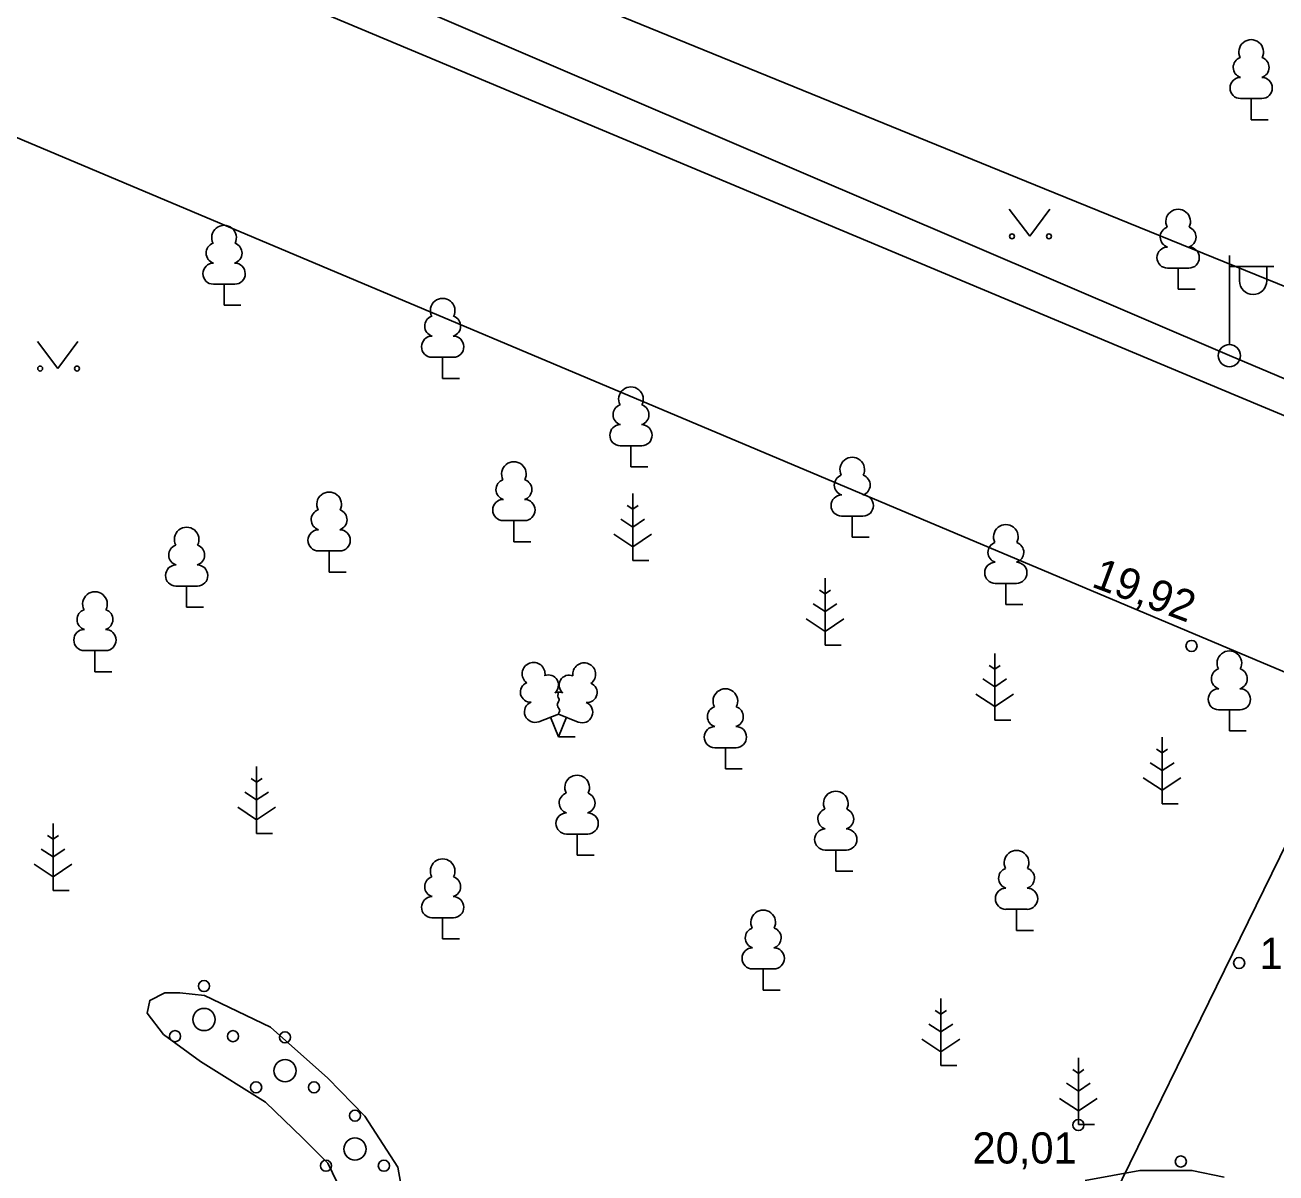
# Model space of a CAD drawing. Extents: x 713497 to 713863, y 6590062 to 6590327.
# Drawn here: x 713775.3 to 713803.4, y 6590210.37 to 6590236.16 of the extents above; entities that cross this region are included whole.
import ezdxf

# ---------------------------------------------------------------- set-up
doc = ezdxf.new("R2010")
doc.units = 0
for name, color, linetype in [('HALJASTUS', 7, 'Continuous'), ('KORGUS', 7, 'Continuous'), ('KPKAABEL', 7, 'Continuous'), ('MPKAABEL', 7, 'Continuous'), ('POST', 7, 'Continuous'), ('PUU', 7, 'Continuous'), ('SITRASS', 7, 'Continuous'), ('TEE', 7, 'Continuous')]:
    doc.layers.add(name, color=color, linetype=linetype)

msp = doc.modelspace()

# ---------------------------------------------------------------- linework, layer by layer
at = {"layer": 'HALJASTUS'}
for p, q in [((713797.407, 6590232.017), (713797.87, 6590231.41)), ((713797.87, 6590231.41), (713798.316, 6590232.017)), ((713775.577, 6590229.047), (713776.04, 6590228.44)), ((713776.04, 6590228.44), (713776.486, 6590229.047))]:
    msp.add_line(p, q, dxfattribs=at)
for points in [[(713783.87, 6590209.41), (713783.67, 6590210.5), (713782.93, 6590211.65), (713782.1, 6590212.5), (713780.81, 6590213.65), (713779.33, 6590214.36), (713778.78, 6590214.42), (713778.44, 6590214.42), (713778.1, 6590214.25), (713778.04, 6590213.96), (713778.41, 6590213.48), (713779.24, 6590212.88), (713780.7, 6590211.96), (713781.53, 6590211.16), (713782.1, 6590210.59), (713782.42, 6590209.93)], [(713802.23, 6590210.28), (713801.51, 6590210.43), (713800.34, 6590210.43), (713799.11, 6590210.2)]]:
    msp.add_lwpolyline(points, dxfattribs=at)
for centre, radius in [((713797.469, 6590231.41), 0.055), ((713798.298, 6590231.41), 0.055), ((713775.639, 6590228.44), 0.055), ((713776.468, 6590228.44), 0.055), ((713779.32, 6590214.57), 0.125), ((713779.32, 6590213.82), 0.25), ((713778.67, 6590213.445), 0.125), ((713779.97, 6590213.445), 0.125), ((713781.14, 6590213.42), 0.125), ((713781.14, 6590212.67), 0.25), ((713780.49, 6590212.295), 0.125), ((713781.79, 6590212.295), 0.125), ((713782.71, 6590211.66), 0.125), ((713782.71, 6590210.91), 0.25), ((713801.26, 6590210.63), 0.125), ((713782.06, 6590210.535), 0.125), ((713783.36, 6590210.535), 0.125)]:
    msp.add_circle(centre, radius, dxfattribs=at)
at = {"layer": 'KORGUS'}
for centre in [(713801.5, 6590222.21), (713802.57, 6590215.09), (713798.96, 6590211.45)]:
    msp.add_circle(centre, 0.125, dxfattribs=at)
at = {"layer": 'KPKAABEL'}
msp.add_lwpolyline([(713794.45, 6590198.59), (713796.04, 6590202.27), (713815.88, 6590242.79)], dxfattribs=at)
at = {"layer": 'MPKAABEL'}
for points in [[(713802.35, 6590228.73), (713777.08, 6590239.56), (713776.78, 6590239.5)], [(713830.25, 6590216.56), (713828.46, 6590217.3), (713809.94, 6590225.53), (713802.35, 6590228.73)]]:
    msp.add_lwpolyline(points, dxfattribs=at)
at = {"layer": 'POST'}
for p, q in [((713802.35, 6590228.98), (713802.35, 6590230.98)), ((713802.35, 6590230.73), (713803.35, 6590230.73)), ((713802.577, 6590230.409), (713802.577, 6590230.73)), ((713803.189, 6590230.409), (713803.189, 6590230.73))]:
    msp.add_line(p, q, dxfattribs=at)
msp.add_circle((713802.35, 6590228.73), 0.25, dxfattribs=at)
msp.add_arc((713802.883, 6590230.409), 0.306, 180, 0, dxfattribs=at)
at = {"layer": 'PUU'}
for p, q in [((713803.08, 6590234.505), (713802.6, 6590234.505)), ((713802.84, 6590234.03), (713802.84, 6590234.505)), ((713803.22, 6590234.03), (713802.84, 6590234.03)), ((713801.44, 6590230.695), (713800.96, 6590230.695)), ((713801.2, 6590230.22), (713801.2, 6590230.695)), ((713780.01, 6590230.335), (713779.53, 6590230.335)), ((713779.77, 6590229.86), (713779.77, 6590230.335)), ((713801.58, 6590230.22), (713801.2, 6590230.22)), ((713780.15, 6590229.86), (713779.77, 6590229.86)), ((713784.92, 6590228.695), (713784.44, 6590228.695)), ((713784.68, 6590228.22), (713784.68, 6590228.695)), ((713785.06, 6590228.22), (713784.68, 6590228.22)), ((713789.15, 6590226.705), (713788.67, 6590226.705)), ((713788.91, 6590226.23), (713788.91, 6590226.705)), ((713789.29, 6590226.23), (713788.91, 6590226.23)), ((713788.95, 6590225.28), (713788.826, 6590225.363)), ((713788.95, 6590225.63), (713788.95, 6590224.13)), ((713789.074, 6590225.363), (713788.95, 6590225.28)), ((713794.12, 6590225.125), (713793.64, 6590225.125)), ((713793.88, 6590224.65), (713793.88, 6590225.125)), ((713786.52, 6590225.025), (713786.04, 6590225.025)), ((713786.28, 6590224.55), (713786.28, 6590225.025)), ((713788.95, 6590224.88), (713788.683, 6590225.058)), ((713789.217, 6590225.058), (713788.95, 6590224.88)), ((713786.66, 6590224.55), (713786.28, 6590224.55)), ((713788.526, 6590224.719), (713788.95, 6590224.437)), ((713788.95, 6590224.437), (713789.374, 6590224.719)), ((713794.26, 6590224.65), (713793.88, 6590224.65)), ((713782.37, 6590224.345), (713781.89, 6590224.345)), ((713782.13, 6590223.87), (713782.13, 6590224.345)), ((713789.31, 6590224.13), (713788.95, 6590224.13)), ((713782.51, 6590223.87), (713782.13, 6590223.87)), ((713793.27, 6590223.73), (713793.27, 6590222.23)), ((713779.17, 6590223.555), (713778.69, 6590223.555)), ((713778.93, 6590223.08), (713778.93, 6590223.555)), ((713793.27, 6590223.38), (713793.146, 6590223.463)), ((713793.394, 6590223.463), (713793.27, 6590223.38)), ((713797.57, 6590223.615), (713797.09, 6590223.615)), ((713797.33, 6590223.14), (713797.33, 6590223.615)), ((713793.27, 6590222.98), (713793.003, 6590223.158)), ((713793.537, 6590223.158), (713793.27, 6590222.98)), ((713797.71, 6590223.14), (713797.33, 6590223.14)), ((713779.31, 6590223.08), (713778.93, 6590223.08)), ((713792.846, 6590222.819), (713793.27, 6590222.537)), ((713793.27, 6590222.537), (713793.694, 6590222.819)), ((713777.11, 6590222.105), (713776.63, 6590222.105)), ((713776.87, 6590221.63), (713776.87, 6590222.105)), ((713793.63, 6590222.23), (713793.27, 6590222.23)), ((713797.08, 6590222.04), (713797.08, 6590220.54)), ((713797.08, 6590221.69), (713796.956, 6590221.773)), ((713797.204, 6590221.773), (713797.08, 6590221.69)), ((713777.25, 6590221.63), (713776.87, 6590221.63)), ((713797.08, 6590221.29), (713796.813, 6590221.468)), ((713797.347, 6590221.468), (713797.08, 6590221.29)), ((713796.656, 6590221.129), (713797.08, 6590220.847)), ((713797.08, 6590220.847), (713797.504, 6590221.129)), ((713786.84, 6590220.505), (713787.285, 6590220.68)), ((713787.28, 6590220.17), (713787.105, 6590220.61)), ((713787.28, 6590220.17), (713787.46, 6590220.61)), ((713787.285, 6590220.68), (713787.725, 6590220.5)), ((713802.59, 6590220.775), (713802.11, 6590220.775)), ((713802.35, 6590220.3), (713802.35, 6590220.775)), ((713797.44, 6590220.54), (713797.08, 6590220.54)), ((713787.66, 6590220.17), (713787.28, 6590220.17)), ((713800.84, 6590220.16), (713800.84, 6590218.66)), ((713802.73, 6590220.3), (713802.35, 6590220.3)), ((713791.27, 6590219.925), (713790.79, 6590219.925)), ((713791.03, 6590219.45), (713791.03, 6590219.925)), ((713800.84, 6590219.81), (713800.716, 6590219.893)), ((713800.964, 6590219.893), (713800.84, 6590219.81)), ((713780.5, 6590219.5), (713780.5, 6590218)), ((713800.84, 6590219.41), (713800.573, 6590219.588)), ((713801.107, 6590219.588), (713800.84, 6590219.41)), ((713780.5, 6590219.15), (713780.376, 6590219.233)), ((713780.624, 6590219.233), (713780.5, 6590219.15)), ((713791.41, 6590219.45), (713791.03, 6590219.45)), ((713800.416, 6590219.249), (713800.84, 6590218.967)), ((713800.84, 6590218.967), (713801.264, 6590219.249)), ((713780.5, 6590218.75), (713780.233, 6590218.928)), ((713780.767, 6590218.928), (713780.5, 6590218.75)), ((713801.2, 6590218.66), (713800.84, 6590218.66)), ((713780.076, 6590218.589), (713780.5, 6590218.307)), ((713780.5, 6590218.307), (713780.924, 6590218.589)), ((713775.93, 6590218.22), (713775.93, 6590216.72)), ((713775.93, 6590217.87), (713775.806, 6590217.953)), ((713776.054, 6590217.953), (713775.93, 6590217.87)), ((713780.86, 6590218), (713780.5, 6590218)), ((713787.94, 6590217.985), (713787.46, 6590217.985)), ((713787.7, 6590217.51), (713787.7, 6590217.985)), ((713775.93, 6590217.47), (713775.663, 6590217.648)), ((713776.197, 6590217.648), (713775.93, 6590217.47)), ((713788.08, 6590217.51), (713787.7, 6590217.51)), ((713793.75, 6590217.625), (713793.27, 6590217.625)), ((713793.51, 6590217.15), (713793.51, 6590217.625)), ((713775.506, 6590217.309), (713775.93, 6590217.027)), ((713775.93, 6590217.027), (713776.354, 6590217.309)), ((713793.89, 6590217.15), (713793.51, 6590217.15)), ((713776.29, 6590216.72), (713775.93, 6590216.72)), ((713784.92, 6590216.105), (713784.44, 6590216.105)), ((713784.68, 6590215.63), (713784.68, 6590216.105)), ((713797.81, 6590216.295), (713797.33, 6590216.295)), ((713797.57, 6590215.82), (713797.57, 6590216.295)), ((713797.95, 6590215.82), (713797.57, 6590215.82)), ((713785.06, 6590215.63), (713784.68, 6590215.63)), ((713792.12, 6590214.955), (713791.64, 6590214.955)), ((713791.88, 6590214.48), (713791.88, 6590214.955)), ((713792.26, 6590214.48), (713791.88, 6590214.48)), ((713795.87, 6590214.29), (713795.87, 6590212.79)), ((713795.87, 6590213.94), (713795.746, 6590214.023)), ((713795.994, 6590214.023), (713795.87, 6590213.94)), ((713795.87, 6590213.54), (713795.603, 6590213.718)), ((713796.137, 6590213.718), (713795.87, 6590213.54)), ((713795.446, 6590213.379), (713795.87, 6590213.097)), ((713795.87, 6590213.097), (713796.294, 6590213.379)), ((713796.23, 6590212.79), (713795.87, 6590212.79)), ((713798.96, 6590212.96), (713798.96, 6590211.46)), ((713798.96, 6590212.61), (713798.836, 6590212.693)), ((713799.084, 6590212.693), (713798.96, 6590212.61)), ((713798.96, 6590212.21), (713798.693, 6590212.388)), ((713799.227, 6590212.388), (713798.96, 6590212.21)), ((713798.536, 6590212.049), (713798.96, 6590211.767)), ((713798.96, 6590211.767), (713799.384, 6590212.049)), ((713799.32, 6590211.46), (713798.96, 6590211.46))]:
    msp.add_line(p, q, dxfattribs=at)
msp.add_lwpolyline([(713787.285, 6590221.175), (713787.265, 6590221.1), (713787.265, 6590221.08), (713787.275, 6590221.05), (713787.295, 6590221.015), (713787.3, 6590220.995), (713787.285, 6590220.96), (713787.26, 6590220.91), (713787.255, 6590220.885), (713787.26, 6590220.87), (713787.27, 6590220.84), (713787.305, 6590220.78), (713787.31, 6590220.76), (713787.305, 6590220.74), (713787.29, 6590220.705), (713787.285, 6590220.68)], dxfattribs=at)
for centre, radius, start, end in [((713802.84, 6590235.55), 0.277, 332.5799, 207.4201), ((713802.67, 6590235.203), 0.233, 109.0217, 253.1415), ((713803.01, 6590235.203), 0.233, 286.8508, 70.9859), ((713802.603, 6590234.742), 0.238, 90.0016, 269.3953), ((713803.077, 6590234.742), 0.238, 270.6047, 89.9984), ((713801.2, 6590231.74), 0.277, 332.5799, 207.4201), ((713779.77, 6590231.38), 0.277, 332.5799, 207.4201), ((713801.03, 6590231.393), 0.233, 109.0217, 253.1415), ((713801.37, 6590231.393), 0.233, 286.8508, 70.9859), ((713779.6, 6590231.033), 0.233, 109.0217, 253.1415), ((713779.94, 6590231.033), 0.233, 286.8508, 70.9859), ((713800.963, 6590230.932), 0.238, 90.0016, 269.3953), ((713801.437, 6590230.932), 0.238, 270.6047, 89.9984), ((713779.533, 6590230.572), 0.238, 90.0016, 269.3953), ((713780.007, 6590230.572), 0.238, 270.6047, 89.9984), ((713784.68, 6590229.74), 0.277, 332.5799, 207.4201), ((713784.51, 6590229.393), 0.233, 109.0217, 253.1415), ((713784.85, 6590229.393), 0.233, 286.8508, 70.9859), ((713784.443, 6590228.932), 0.238, 90.0016, 269.3953), ((713784.917, 6590228.932), 0.238, 270.6047, 89.9984), ((713788.91, 6590227.75), 0.277, 332.5799, 207.4201), ((713788.74, 6590227.403), 0.233, 109.0217, 253.1415), ((713789.08, 6590227.403), 0.233, 286.8508, 70.9859), ((713788.673, 6590226.942), 0.238, 90.0016, 269.3953), ((713789.147, 6590226.942), 0.238, 270.6047, 89.9984), ((713786.28, 6590226.07), 0.277, 332.5799, 207.4201), ((713793.88, 6590226.17), 0.277, 332.5799, 207.4201), ((713786.11, 6590225.723), 0.233, 109.0217, 253.1415), ((713786.45, 6590225.723), 0.233, 286.8508, 70.9859), ((713793.71, 6590225.823), 0.233, 109.0217, 253.1415), ((713794.05, 6590225.823), 0.233, 286.8508, 70.9859), ((713782.13, 6590225.39), 0.277, 332.5799, 207.4201), ((713786.043, 6590225.262), 0.238, 90.0016, 269.3953), ((713786.517, 6590225.262), 0.238, 270.6047, 89.9984), ((713793.643, 6590225.362), 0.238, 90.0016, 269.3953), ((713794.117, 6590225.362), 0.238, 270.6047, 89.9984), ((713781.96, 6590225.043), 0.233, 109.0217, 253.1415), ((713782.3, 6590225.043), 0.233, 286.8508, 70.9859), ((713778.93, 6590224.6), 0.277, 332.5799, 207.4201), ((713781.893, 6590224.582), 0.238, 90.0016, 269.3953), ((713782.367, 6590224.582), 0.238, 270.6047, 89.9984), ((713797.33, 6590224.66), 0.277, 332.5799, 207.4201), ((713797.16, 6590224.313), 0.233, 109.0217, 253.1415), ((713797.5, 6590224.313), 0.233, 286.8508, 70.9859), ((713778.76, 6590224.253), 0.233, 109.0217, 253.1415), ((713779.1, 6590224.253), 0.233, 286.8508, 70.9859), ((713778.693, 6590223.792), 0.238, 90.0016, 269.3953), ((713779.167, 6590223.792), 0.238, 270.6047, 89.9984), ((713797.093, 6590223.852), 0.238, 90.0016, 269.3953), ((713797.567, 6590223.852), 0.238, 270.6047, 89.9984), ((713776.87, 6590223.15), 0.277, 332.5799, 207.4201), ((713776.7, 6590222.803), 0.233, 109.0217, 253.1415), ((713777.04, 6590222.803), 0.233, 286.8508, 70.9859), ((713776.633, 6590222.342), 0.238, 90.0016, 269.3953), ((713777.107, 6590222.342), 0.238, 270.6047, 89.9984), ((713802.35, 6590221.82), 0.277, 332.5799, 207.4201), ((713786.723, 6590221.584), 0.256, 111.5027, 232.5173), ((713786.723, 6590221.584), 0.256, 350.4856, 111.5002), ((713787.859, 6590221.575), 0.256, 67.6168, 188.6314), ((713787.859, 6590221.575), 0.256, 306.5997, 67.6143), ((713787.058, 6590221.334), 0.224, 308.5041, 111.5725), ((713787.521, 6590221.329), 0.225, 67.7016, 230.5126), ((713802.18, 6590221.473), 0.233, 109.0217, 253.1415), ((713802.52, 6590221.473), 0.233, 286.8508, 70.9859), ((713786.649, 6590221.173), 0.224, 111.4304, 274.4987), ((713787.284, 6590220.937), 0.237, 66.7655, 111.5015), ((713787.926, 6590221.163), 0.224, 264.6183, 67.6866), ((713791.03, 6590220.97), 0.277, 332.5799, 207.4201), ((713802.113, 6590221.012), 0.238, 90.0016, 269.3953), ((713802.587, 6590221.012), 0.238, 270.6047, 89.9984), ((713786.754, 6590220.728), 0.237, 111.5014, 291.5004), ((713787.815, 6590220.72), 0.237, 247.6166, 67.6155), ((713790.86, 6590220.623), 0.233, 109.0217, 253.1415), ((713791.2, 6590220.623), 0.233, 286.8508, 70.9859), ((713790.793, 6590220.162), 0.238, 90.0016, 269.3953), ((713791.267, 6590220.162), 0.238, 270.6047, 89.9984), ((713787.7, 6590219.03), 0.277, 332.5799, 207.4201), ((713787.53, 6590218.683), 0.233, 109.0217, 253.1415), ((713787.87, 6590218.683), 0.233, 286.8508, 70.9859), ((713793.51, 6590218.67), 0.277, 332.5799, 207.4201), ((713787.463, 6590218.222), 0.238, 90.0016, 269.3953), ((713787.937, 6590218.222), 0.238, 270.6047, 89.9984), ((713793.34, 6590218.323), 0.233, 109.0217, 253.1415), ((713793.68, 6590218.323), 0.233, 286.8508, 70.9859), ((713793.273, 6590217.862), 0.238, 90.0016, 269.3953), ((713793.747, 6590217.862), 0.238, 270.6047, 89.9984), ((713797.57, 6590217.34), 0.277, 332.5799, 207.4201), ((713784.68, 6590217.15), 0.277, 332.5799, 207.4201), ((713797.4, 6590216.993), 0.233, 109.0217, 253.1415), ((713797.74, 6590216.993), 0.233, 286.8508, 70.9859), ((713784.51, 6590216.803), 0.233, 109.0217, 253.1415), ((713784.85, 6590216.803), 0.233, 286.8508, 70.9859), ((713797.333, 6590216.532), 0.238, 90.0016, 269.3953), ((713797.807, 6590216.532), 0.238, 270.6047, 89.9984), ((713784.443, 6590216.342), 0.238, 90.0016, 269.3953), ((713784.917, 6590216.342), 0.238, 270.6047, 89.9984), ((713791.88, 6590216), 0.277, 332.5799, 207.4201), ((713791.71, 6590215.653), 0.233, 109.0217, 253.1415), ((713792.05, 6590215.653), 0.233, 286.8508, 70.9859), ((713791.643, 6590215.192), 0.238, 90.0016, 269.3953), ((713792.117, 6590215.192), 0.238, 270.6047, 89.9984)]:
    msp.add_arc(centre, radius, start, end, dxfattribs=at)
at = {"layer": 'SITRASS'}
msp.add_lwpolyline([(713863.358, 6590205.976), (713841.44, 6590214.83), (713823.81, 6590222.07), (713798.2, 6590232.48), (713769.43, 6590244.2), (713757.31, 6590249.39), (713740.65, 6590256.05), (713706.71, 6590269.85)], dxfattribs=at)
at = {"layer": 'TEE'}
for points in [[(713705.99, 6590269.548), (713709.56, 6590266.765), (713802.48, 6590227.84), (713863.358, 6590202.427)], [(713863.358, 6590196.431), (713764.059, 6590238.297), (713742.86, 6590246.85), (713734.952, 6590249.165), (713734.699, 6590248.565), (713734.18, 6590247.457), (713733.715, 6590246.43), (713733.203, 6590245.297), (713732.677, 6590244.133), (713734.573, 6590241.161), (713736.147, 6590238.694), (713748.431, 6590232.928), (713760.369, 6590227.324), (713754.579, 6590213.72), (713745.812, 6590217.88), (713744.782, 6590218.369), (713743.276, 6590218.882), (713741.882, 6590218.856), (713740.847, 6590218.526), (713739.892, 6590217.92), (713738.92, 6590215.76), (713731.142, 6590198.62)]]:
    msp.add_lwpolyline(points, dxfattribs=at)

# ---------------------------------------------------------------- texts
at = {"layer": 'KORGUS'}
msp.add_text('19,92', height=0.7, rotation=339.5058, dxfattribs=at).set_placement((713799.228, 6590223.549))
for s, p in [('19,82', (713803.028, 6590214.955)), ('20,01', (713796.58, 6590210.585))]:
    msp.add_text(s, height=0.7, dxfattribs=at).set_placement(p)

doc.saveas('drawing.dxf')
